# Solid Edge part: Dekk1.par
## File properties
Author: Egon 815
Template: Normal.par
Last saved by: Egon 815
Revision: 11
Application: Solid Edge
Accuracy: 0,990
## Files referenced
..\Laev.asm
.C:\Kool\3D Modelleerimine\LaevaJoonis\Laev.asm
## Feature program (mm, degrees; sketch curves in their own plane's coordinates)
sketch for "unnamed Protrusion 1" plane through (0, 0, 5032.5774) normal (0, 0, 1) x-axis (1, 0, 0)
  line (12545.0272, -41255.0792) -> (11284.8293, -32564.0587)
  line (11284.8293, -32564.0587) -> (12545.0272, -30130.5729)
  line (12545.0272, -30130.5729) -> (11284.8293, -24481.4096)
  line (11284.8293, -24481.4096) -> (12545.0272, -21048.4565)
  line (12545.0272, -21048.4565) -> (11284.8293, -17658.9585)
  line (11284.8293, -17658.9585) -> (12545.0272, -12531.2564)
  line (12545.0272, -12531.2564) -> (11284.8293, -7925.0156)
  line (11284.8293, -7925.0156) -> (13848.6803, -4752.7931)
  line (13848.6803, -4752.7931) -> (13848.6803, 8153.3723)
  line (13848.6803, 8153.3723) -> (13848.6803, 14715.0928)
  line (13848.6803, 14715.0928) -> (11740.6294, 16682.9335)
  line (11740.6294, 16682.9335) -> (11740.6294, 21557.9073)
  line (11740.6294, 21557.9073) -> (10311.1258, 24123.683)
  line (10311.1258, 24123.683) -> (10311.1258, 45639.5451)
  line (10311.1258, 45639.5451) -> (6535.7701, 45639.5451)
  line (6535.7701, 45639.5451) -> (6535.7701, 52017.3304)
  line (6535.7701, 52017.3304) -> (4263.2259, 55939.3019)
  line (4263.2259, 55939.3019) -> (0, 55939.3019)
  line (-4263.2259, 55939.3019) -> (0, 55939.3019)
  line (-6535.7701, 52017.3304) -> (-4263.2259, 55939.3019)
  line (-6535.7701, 45639.5451) -> (-6535.7701, 52017.3304)
  line (-10311.1258, 45639.5451) -> (-6535.7701, 45639.5451)
  line (-10311.1258, 24123.683) -> (-10311.1258, 45639.5451)
  line (-11740.6294, 21557.9073) -> (-10311.1258, 24123.683)
  line (-11740.6294, 16682.9335) -> (-11740.6294, 21557.9073)
  line (-13848.6803, 14715.0928) -> (-11740.6294, 16682.9335)
  line (-13848.6803, 8153.3723) -> (-13848.6803, 14715.0928)
  line (-13848.6803, -4752.7931) -> (-13848.6803, 8153.3723)
  line (-11284.8293, -7925.0156) -> (-13848.6803, -4752.7931)
  line (-12545.0272, -12531.2564) -> (-11284.8293, -7925.0156)
  line (-11284.8293, -17658.9585) -> (-12545.0272, -12531.2564)
  line (-12545.0272, -21048.4565) -> (-11284.8293, -17658.9585)
  line (-11284.8293, -24481.4096) -> (-12545.0272, -21048.4565)
  line (-12545.0272, -30130.5729) -> (-11284.8293, -24481.4096)
  line (-11284.8293, -32564.0587) -> (-12545.0272, -30130.5729)
  line (-12545.0272, -41255.0792) -> (-11284.8293, -32564.0587)
  line (-10719.9129, -43601.6547) -> (-12545.0272, -41255.0792)
  line (-11156.3293, -59033.8334) -> (-10719.9129, -43601.6547)
  line (-11156.3293, -59033.8334) -> (11156.3293, -59033.8334)
  line (11156.3293, -59033.8334) -> (10719.9129, -43601.6547)
  line (10719.9129, -43601.6547) -> (12545.0272, -41255.0792)
extrude "unnamed Protrusion 1" add to key point along +normal
sketch for "unnamed Protrusion 2" plane through (0, 0, 5032.5774) normal (0, 0, 1) x-axis (1, 0, 0)
  line (11156.3293, -59033.8334) -> (10270.8716, -66244.3403)
  line (10270.8716, -66244.3403) -> (0, -66244.3403)
  line (-10270.8716, -66244.3403) -> (0, -66244.3403)
  line (-11156.3293, -59033.8334) -> (-10270.8716, -66244.3403)
extrude "unnamed Protrusion 2" add to key point along +normal
sketch for "unnamed Cutout 1" plane through (0, 0, 0) normal (1, 0, 0) x-axis (0, 1, 0)
extrude "unnamed Cutout 1" cut through
logasc func "Lip_Groove_2"  LipOrGrooveWidth = 60 mm; LipOrGrooveHeight = 1000 mm
sketch for "ExtrudedCutout_27" #1 plane through (0, 0, 0) normal (1, 0, 0) x-axis (0, 1, 0)
  line (54069.4125, 7684.8312) -> (54069.4125, 7184.8312)
  line (54069.4125, 7184.8312) -> (55069.4125, 7184.8312)
  line (55069.4125, 7184.8312) -> (55069.4125, 7684.8312)
  line (55069.4125, 7684.8312) -> (54069.4125, 7684.8312)
sketch for "ExtrudedCutout_27" #2 plane through (0, 0, 0) normal (1, 0, 0) x-axis (0, 1, 0)
  line (48157.7088, 7684.8312) -> (48157.7088, 7184.8312)
  line (48157.7088, 7184.8312) -> (49157.7088, 7184.8312)
  line (49157.7088, 7184.8312) -> (49157.7088, 7684.8312)
  line (49157.7088, 7684.8312) -> (48157.7088, 7684.8312)
sketch for "ExtrudedCutout_27" #3 plane through (0, 0, 0) normal (1, 0, 0) x-axis (0, 1, 0)
  line (39675.6639, 7684.8312) -> (39675.6639, 7184.8312)
  line (39675.6639, 7184.8312) -> (40675.6639, 7184.8312)
  line (40675.6639, 7184.8312) -> (40675.6639, 7684.8312)
  line (40675.6639, 7684.8312) -> (39675.6639, 7684.8312)
sketch for "ExtrudedCutout_27" #4 plane through (0, 0, 0) normal (1, 0, 0) x-axis (0, 1, 0)
  line (30914.1944, 7684.8312) -> (30914.1944, 7184.8312)
  line (30914.1944, 7184.8312) -> (31914.1944, 7184.8312)
  line (31914.1944, 7184.8312) -> (31914.1944, 7684.8312)
  line (31914.1944, 7684.8312) -> (30914.1944, 7684.8312)
sketch for "ExtrudedCutout_27" #5 plane through (0, 0, 0) normal (1, 0, 0) x-axis (0, 1, 0)
  line (21057.9073, 7684.8312) -> (21057.9073, 7184.8312)
  line (21057.9073, 7184.8312) -> (22057.9073, 7184.8312)
  line (22057.9073, 7184.8312) -> (22057.9073, 7684.8312)
  line (22057.9073, 7684.8312) -> (21057.9073, 7684.8312)
sketch for "ExtrudedCutout_27" #6 plane through (0, 0, 0) normal (1, 0, 0) x-axis (0, 1, 0)
  line (15215.0928, 7684.8312) -> (14215.0928, 7684.8312)
  line (14215.0928, 7684.8312) -> (14215.0928, 7184.8312)
  line (14215.0928, 7184.8312) -> (15215.0928, 7184.8312)
  line (15215.0928, 7184.8312) -> (15215.0928, 7684.8312)
sketch for "ExtrudedCutout_27" #7 plane through (0, 0, 0) normal (1, 0, 0) x-axis (0, 1, 0)
  line (7386.6022, 7684.8312) -> (7386.6022, 7184.8312)
  line (7386.6022, 7184.8312) -> (8386.6022, 7184.8312)
  line (8386.6022, 7184.8312) -> (8386.6022, 7684.8312)
  line (8386.6022, 7684.8312) -> (7386.6022, 7684.8312)
sketch for "ExtrudedCutout_27" #8 plane through (0, 0, 0) normal (1, 0, 0) x-axis (0, 1, 0)
  line (1429.7383, 7684.8312) -> (429.7383, 7684.8312)
  line (429.7383, 7684.8312) -> (429.7383, 7184.8312)
  line (429.7383, 7184.8312) -> (1429.7383, 7184.8312)
  line (1429.7383, 7184.8312) -> (1429.7383, 7684.8312)
sketch for "ExtrudedCutout_27" #9 plane through (0, 0, 0) normal (1, 0, 0) x-axis (0, 1, 0)
  line (-5252.7931, 7684.8312) -> (-5252.7931, 7184.8312)
  line (-5252.7931, 7184.8312) -> (-4252.7931, 7184.8312)
  line (-4252.7931, 7184.8312) -> (-4252.7931, 7684.8312)
  line (-4252.7931, 7684.8312) -> (-5252.7931, 7684.8312)
sketch for "ExtrudedCutout_27" #10 plane through (0, 0, 0) normal (1, 0, 0) x-axis (0, 1, 0)
  line (-13031.2564, 7684.8312) -> (-13031.2564, 7184.8312)
  line (-13031.2564, 7184.8312) -> (-12031.2564, 7184.8312)
  line (-12031.2564, 7184.8312) -> (-12031.2564, 7684.8312)
  line (-12031.2564, 7684.8312) -> (-13031.2564, 7684.8312)
sketch for "ExtrudedCutout_27" #11 plane through (0, 0, 0) normal (1, 0, 0) x-axis (0, 1, 0)
  line (-21548.4565, 7684.8312) -> (-21548.4565, 7184.8312)
  line (-21548.4565, 7184.8312) -> (-20548.4565, 7184.8312)
  line (-20548.4565, 7184.8312) -> (-20548.4565, 7684.8312)
  line (-20548.4565, 7684.8312) -> (-21548.4565, 7684.8312)
sketch for "ExtrudedCutout_27" #12 plane through (0, 0, 0) normal (1, 0, 0) x-axis (0, 1, 0)
  line (-29630.5729, 7684.8312) -> (-30630.5729, 7684.8312)
  line (-30630.5729, 7684.8312) -> (-30630.5729, 7184.8312)
  line (-30630.5729, 7184.8312) -> (-29630.5729, 7184.8312)
  line (-29630.5729, 7184.8312) -> (-29630.5729, 7684.8312)
sketch for "ExtrudedCutout_27" #13 plane through (0, 0, 0) normal (1, 0, 0) x-axis (0, 1, 0)
  line (-40755.0792, 7684.8312) -> (-41755.0792, 7684.8312)
  line (-41755.0792, 7684.8312) -> (-41755.0792, 7184.8312)
  line (-41755.0792, 7184.8312) -> (-40755.0792, 7184.8312)
  line (-40755.0792, 7184.8312) -> (-40755.0792, 7684.8312)
sketch for "ExtrudedCutout_27" #14 plane through (0, 0, 0) normal (1, 0, 0) x-axis (0, 1, 0)
  line (-48390.7397, 7684.8312) -> (-48390.7397, 7184.8312)
  line (-48390.7397, 7184.8312) -> (-47390.7397, 7184.8312)
  line (-47390.7397, 7184.8312) -> (-47390.7397, 7684.8312)
  line (-47390.7397, 7684.8312) -> (-48390.7397, 7684.8312)
sketch for "ExtrudedCutout_27" #15 plane through (0, 0, 0) normal (1, 0, 0) x-axis (0, 1, 0)
  line (-55080.6119, 7684.8312) -> (-55080.6119, 7184.8312)
  line (-55080.6119, 7184.8312) -> (-54080.6119, 7184.8312)
  line (-54080.6119, 7184.8312) -> (-54080.6119, 7684.8312)
  line (-54080.6119, 7684.8312) -> (-55080.6119, 7684.8312)
extrude "ExtrudedCutout_27" cut finite symmetric
sketch for "unnamed Protrusion 3" plane through (0, 0, 6900) normal (0, 0, 1) x-axis (1, 0, 0)
  circle centre (0, 48625.6415) radius 5447.2462
extrude "unnamed Protrusion 3" add to key point along +normal
chamfer "Chamfer_1" setback 450
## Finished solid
Body 1: solid body, 173 faces, 637 edges, 422 vertices.
  Faces by surface: plane 171, cone 1, cylinder 1
  Edges by curve: line 634, circle 3
Bounding box of the edges (mm): 27697.361 x 122183.642 x 4422.029, from (-13848.6803, -66244.3403, 5032.5774) to (13848.6803, 55939.3019, 9454.6062).
Cylindrical faces by radius (mm): R5447.2462 x1
Conical faces (half-angle, radius in mm at the cone's reference point): 45 deg R5447.2462 x1
Planar faces by outward normal: +x 8, +y 33, +z 3, -x 8, -y 33, -z 31, oblique 55
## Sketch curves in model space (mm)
circle centre (0, 48625.6415, 6900) radius 4953.3647
circle centre (0, 48625.6415, 6900) radius 5447.2462
line (0, 55939.3019, 6900) -> (0, 42480.3282, 6900)
line (0, 22057.9073, 7684.8312) -> (0, 21057.9073, 7684.8312)
line (0, 21057.9073, 7684.8312) -> (0, 21057.9073, 7184.8312)
line (0, 21057.9073, 7184.8312) -> (0, 22057.9073, 7184.8312)
line (0, 22057.9073, 7184.8312) -> (0, 22057.9073, 7684.8312)
line (0, 55069.4125, 7684.8312) -> (0, 54069.4125, 7684.8312)
line (0, 54069.4125, 7684.8312) -> (0, 54069.4125, 7184.8312)
line (0, 54069.4125, 7184.8312) -> (0, 55069.4125, 7184.8312)
line (0, 55069.4125, 7184.8312) -> (0, 55069.4125, 7684.8312)
line (0, 40675.6639, 7684.8312) -> (0, 39675.6639, 7684.8312)
line (0, 39675.6639, 7684.8312) -> (0, 39675.6639, 7184.8312)
line (0, 39675.6639, 7184.8312) -> (0, 40675.6639, 7184.8312)
line (0, 40675.6639, 7184.8312) -> (0, 40675.6639, 7684.8312)
line (0, -54080.6119, 7684.8312) -> (0, -55080.6119, 7684.8312)
line (0, -55080.6119, 7684.8312) -> (0, -55080.6119, 7184.8312)
line (0, -55080.6119, 7184.8312) -> (0, -54080.6119, 7184.8312)
line (0, -54080.6119, 7184.8312) -> (0, -54080.6119, 7684.8312)
line (0, 8386.6022, 7684.8312) -> (0, 7386.6022, 7684.8312)
line (0, 7386.6022, 7684.8312) -> (0, 7386.6022, 7184.8312)
line (0, 7386.6022, 7184.8312) -> (0, 8386.6022, 7184.8312)
line (0, 8386.6022, 7184.8312) -> (0, 8386.6022, 7684.8312)
line (0, -12031.2564, 7684.8312) -> (0, -13031.2564, 7684.8312)
line (0, -13031.2564, 7684.8312) -> (0, -13031.2564, 7184.8312)
line (0, -13031.2564, 7184.8312) -> (0, -12031.2564, 7184.8312)
line (0, -12031.2564, 7184.8312) -> (0, -12031.2564, 7684.8312)
line (0, -20548.4565, 7684.8312) -> (0, -21548.4565, 7684.8312)
line (0, -21548.4565, 7684.8312) -> (0, -21548.4565, 7184.8312)
line (0, -21548.4565, 7184.8312) -> (0, -20548.4565, 7184.8312)
line (0, -20548.4565, 7184.8312) -> (0, -20548.4565, 7684.8312)
line (0, -29630.5729, 7684.8312) -> (0, -30630.5729, 7684.8312)
line (0, -30630.5729, 7684.8312) -> (0, -30630.5729, 7184.8312)
line (0, -30630.5729, 7184.8312) -> (0, -29630.5729, 7184.8312)
line (0, -29630.5729, 7184.8312) -> (0, -29630.5729, 7684.8312)
line (0, -40755.0792, 7684.8312) -> (0, -41755.0792, 7684.8312)
line (0, -41755.0792, 7684.8312) -> (0, -41755.0792, 7184.8312)
line (0, -41755.0792, 7184.8312) -> (0, -40755.0792, 7184.8312)
line (0, -40755.0792, 7184.8312) -> (0, -40755.0792, 7684.8312)
line (0, -47390.7397, 7684.8312) -> (0, -48390.7397, 7684.8312)
line (0, -48390.7397, 7684.8312) -> (0, -48390.7397, 7184.8312)
line (0, -48390.7397, 7184.8312) -> (0, -47390.7397, 7184.8312)
line (0, -47390.7397, 7184.8312) -> (0, -47390.7397, 7684.8312)
line (0, -4252.7931, 7684.8312) -> (0, -5252.7931, 7684.8312)
line (0, -5252.7931, 7684.8312) -> (0, -5252.7931, 7184.8312)
line (0, -5252.7931, 7184.8312) -> (0, -4252.7931, 7184.8312)
line (0, -4252.7931, 7184.8312) -> (0, -4252.7931, 7684.8312)
line (0, 15215.0928, 7684.8312) -> (0, 14215.0928, 7684.8312)
line (0, 14215.0928, 7684.8312) -> (0, 14215.0928, 7184.8312)
line (0, 14215.0928, 7184.8312) -> (0, 15215.0928, 7184.8312)
line (0, 15215.0928, 7184.8312) -> (0, 15215.0928, 7684.8312)
line (0, 1429.7383, 7684.8312) -> (0, 429.7383, 7684.8312)
line (0, 429.7383, 7684.8312) -> (0, 429.7383, 7184.8312)
line (0, 429.7383, 7184.8312) -> (0, 1429.7383, 7184.8312)
line (0, 1429.7383, 7184.8312) -> (0, 1429.7383, 7684.8312)
line (0, 49157.7088, 7684.8312) -> (0, 48157.7088, 7684.8312)
line (0, 48157.7088, 7684.8312) -> (0, 48157.7088, 7184.8312)
line (0, 48157.7088, 7184.8312) -> (0, 49157.7088, 7184.8312)
line (0, 49157.7088, 7184.8312) -> (0, 49157.7088, 7684.8312)
line (0, 31914.1944, 7684.8312) -> (0, 30914.1944, 7684.8312)
line (0, 30914.1944, 7684.8312) -> (0, 30914.1944, 7184.8312)
line (0, 30914.1944, 7184.8312) -> (0, 31914.1944, 7184.8312)
line (0, 31914.1944, 7184.8312) -> (0, 31914.1944, 7684.8312)
line (0, -59033.8334, 5032.5774) -> (0, -59033.8334, 7184.8312)
line (0, 54458.9392, 7184.8312) -> (0, 54458.9392, 5032.5774)
line (0, -66244.3403, 7184.8312) -> (0, 54458.9392, 7184.8312)
line (0, -44381.2454, 5032.5774) -> (0, 120116.3176, 5032.5774)
line (0, -44381.2454, 5032.5774) -> (0, -59033.8334, 5032.5774)
line (0, -59033.8334, 5032.5774) -> (0, -66244.3403, 7184.8312)
line (0, -111469.4186, 8314.9532) -> (0, -66244.3403, 7184.8312)
line (-11156.3293, -59033.8334, 5032.5774) -> (-10270.8716, -66244.3403, 5032.5774)
line (-10270.8716, -66244.3403, 5032.5774) -> (0, -66244.3403, 5032.5774)
line (10270.8716, -66244.3403, 5032.5774) -> (0, -66244.3403, 5032.5774)
line (11156.3293, -59033.8334, 5032.5774) -> (10270.8716, -66244.3403, 5032.5774)
line (10719.9129, -43601.6547, 5032.5774) -> (12545.0272, -41255.0792, 5032.5774)
line (12545.0272, -41255.0792, 5032.5774) -> (11284.8293, -32564.0587, 5032.5774)
line (11284.8293, -32564.0587, 5032.5774) -> (12545.0272, -30130.5729, 5032.5774)
line (12545.0272, -30130.5729, 5032.5774) -> (11284.8293, -24481.4096, 5032.5774)
line (11284.8293, -24481.4096, 5032.5774) -> (12545.0272, -21048.4565, 5032.5774)
line (12545.0272, -21048.4565, 5032.5774) -> (11284.8293, -17658.9585, 5032.5774)
line (11284.8293, -17658.9585, 5032.5774) -> (12545.0272, -12531.2564, 5032.5774)
line (12545.0272, -12531.2564, 5032.5774) -> (11284.8293, -7925.0156, 5032.5774)
line (11284.8293, -7925.0156, 5032.5774) -> (13848.6803, -4752.7931, 5032.5774)
line (13848.6803, -4752.7931, 5032.5774) -> (13848.6803, 8153.3723, 5032.5774)
line (13848.6803, 8153.3723, 5032.5774) -> (13848.6803, 14715.0928, 5032.5774)
line (13848.6803, 14715.0928, 5032.5774) -> (11740.6294, 16682.9335, 5032.5774)
line (11740.6294, 16682.9335, 5032.5774) -> (11740.6294, 21557.9073, 5032.5774)
line (11740.6294, 21557.9073, 5032.5774) -> (10311.1258, 24123.683, 5032.5774)
line (10311.1258, 24123.683, 5032.5774) -> (10311.1258, 45639.5451, 5032.5774)
line (10311.1258, 45639.5451, 5032.5774) -> (6535.7701, 45639.5451, 5032.5774)
line (6535.7701, 45639.5451, 5032.5774) -> (6535.7701, 52017.3304, 5032.5774)
line (6535.7701, 52017.3304, 5032.5774) -> (4263.2259, 55939.3019, 5032.5774)
line (4263.2259, 55939.3019, 5032.5774) -> (0, 55939.3019, 5032.5774)
line (-4263.2259, 55939.3019, 5032.5774) -> (0, 55939.3019, 5032.5774)
line (-6535.7701, 52017.3304, 5032.5774) -> (-4263.2259, 55939.3019, 5032.5774)
line (-6535.7701, 45639.5451, 5032.5774) -> (-6535.7701, 52017.3304, 5032.5774)
line (-10311.1258, 45639.5451, 5032.5774) -> (-6535.7701, 45639.5451, 5032.5774)
line (-10311.1258, 24123.683, 5032.5774) -> (-10311.1258, 45639.5451, 5032.5774)
line (-11740.6294, 21557.9073, 5032.5774) -> (-10311.1258, 24123.683, 5032.5774)
line (-11740.6294, 16682.9335, 5032.5774) -> (-11740.6294, 21557.9073, 5032.5774)
line (-13848.6803, 14715.0928, 5032.5774) -> (-11740.6294, 16682.9335, 5032.5774)
line (-13848.6803, 8153.3723, 5032.5774) -> (-13848.6803, 14715.0928, 5032.5774)
line (-13848.6803, -4752.7931, 5032.5774) -> (-13848.6803, 8153.3723, 5032.5774)
line (-11284.8293, -7925.0156, 5032.5774) -> (-13848.6803, -4752.7931, 5032.5774)
line (-12545.0272, -12531.2564, 5032.5774) -> (-11284.8293, -7925.0156, 5032.5774)
line (-11284.8293, -17658.9585, 5032.5774) -> (-12545.0272, -12531.2564, 5032.5774)
line (-12545.0272, -21048.4565, 5032.5774) -> (-11284.8293, -17658.9585, 5032.5774)
line (-11284.8293, -24481.4096, 5032.5774) -> (-12545.0272, -21048.4565, 5032.5774)
line (-12545.0272, -30130.5729, 5032.5774) -> (-11284.8293, -24481.4096, 5032.5774)
line (-11284.8293, -32564.0587, 5032.5774) -> (-12545.0272, -30130.5729, 5032.5774)
line (-12545.0272, -41255.0792, 5032.5774) -> (-11284.8293, -32564.0587, 5032.5774)
line (-10719.9129, -43601.6547, 5032.5774) -> (-12545.0272, -41255.0792, 5032.5774)
line (-11156.3293, -59033.8334, 5032.5774) -> (-10719.9129, -43601.6547, 5032.5774)
line (-11156.3293, -59033.8334, 5032.5774) -> (11156.3293, -59033.8334, 5032.5774)
line (11156.3293, -59033.8334, 5032.5774) -> (10719.9129, -43601.6547, 5032.5774)
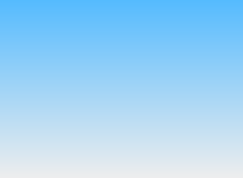
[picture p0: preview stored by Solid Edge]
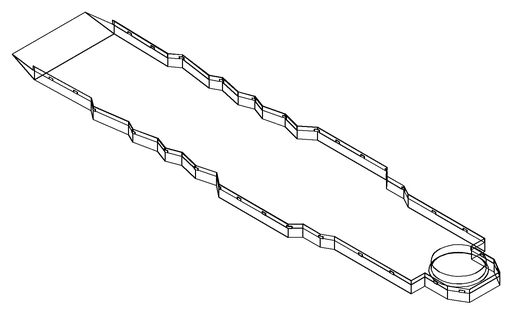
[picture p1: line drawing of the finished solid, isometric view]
